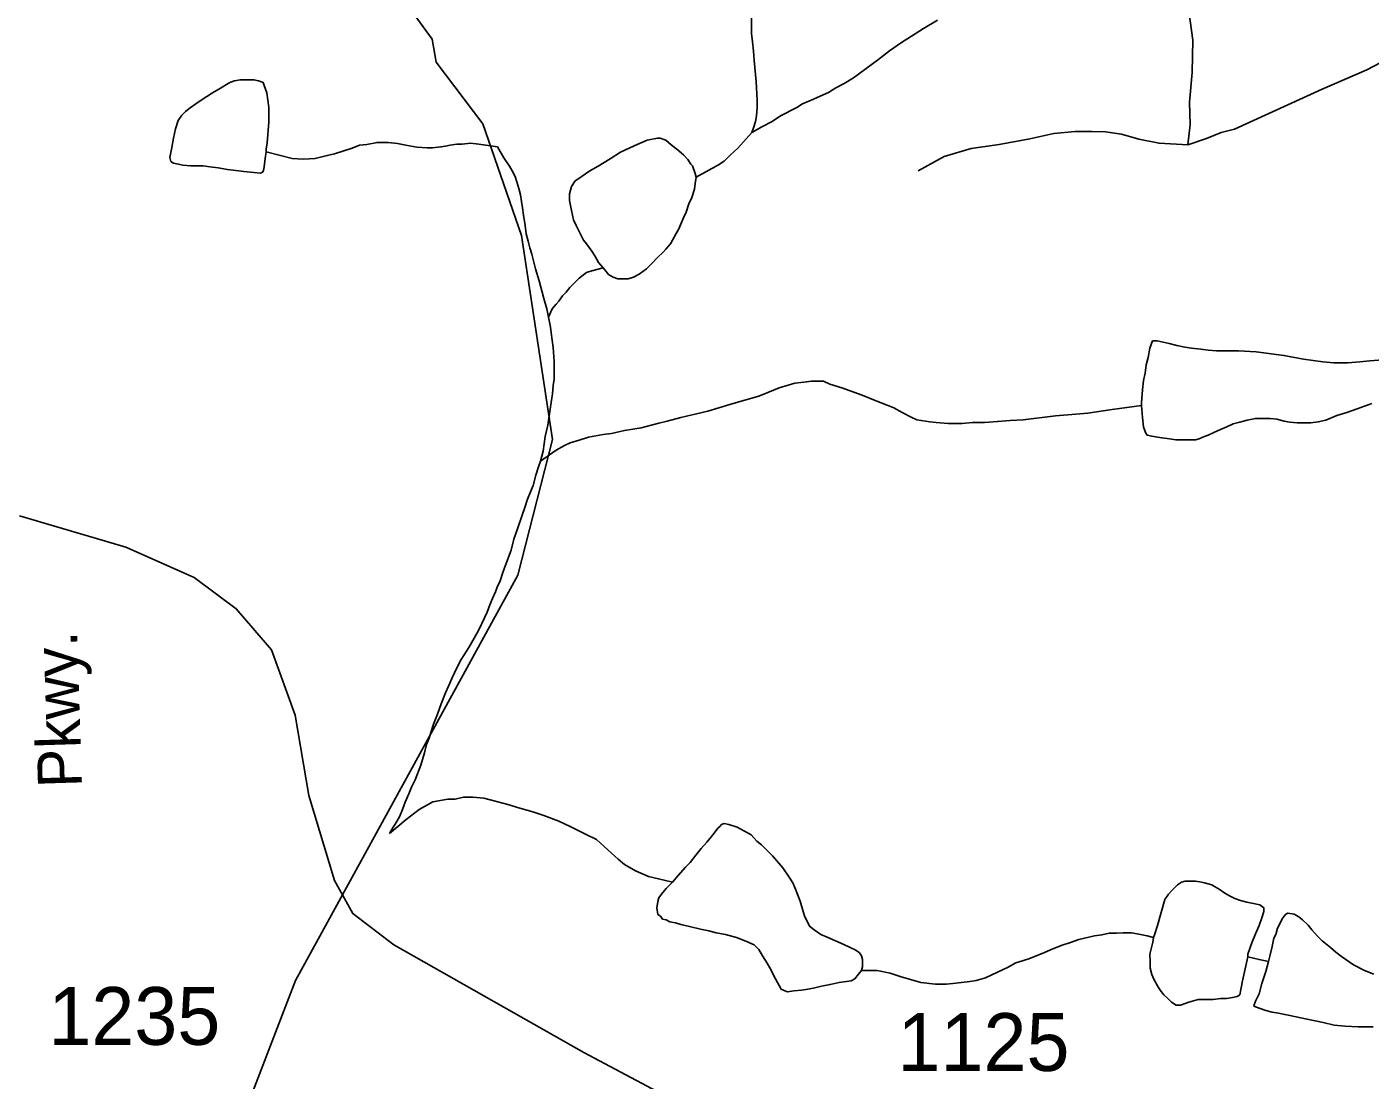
# Model space of a CAD drawing. Extents: x 2001466 to 2224147, y 644118 to 847247.
# Drawn here: x 2043124 to 2046028, y 676608 to 678885 of the extents above; entities that cross this region are included whole.
import ezdxf

# ---------------------------------------------------------------- set-up
doc = ezdxf.new("R2010")
doc.units = 0
for name, color, linetype in [('Exist Hydrographic Creek Single Shore', 7, 'Continuous'), ('Exist Hydrographic Misc Water Feature', 7, 'Continuous'), ('Exist Road Non-System Type 51', 7, 'Continuous'), ('Exist Road Secondary Type 51 Attributed', 7, 'Continuous'), ('Exist Road Secondary Type 51 Label', 7, 'Continuous'), ('Exist Road Secondary Type 51 Number Label', 7, 'Continuous')]:
    doc.layers.add(name, color=color, linetype=linetype)

msp = doc.modelspace()

# ---------------------------------------------------------------- linework, layer by layer
at = {"layer": 'Exist Hydrographic Creek Single Shore'}
for points in [[(2044109.7, 678675.3), (2044008.8, 678808.5), (2044000.8, 678857.9), (2043891.7, 679007.8), (2043766.8, 679272.8)], [(2042616.7, 674673.3), (2042674.7, 674796.8), (2042699.7, 675048.9), (2042799.6, 675214.3), (2043173.6, 675564.3), (2043455.8, 676175.3), (2043704.7, 676823.2), (2044185.7, 677699.3), (2044260.8, 677993), (2044193.7, 678434), (2044109.7, 678675.3)]]:
    msp.add_lwpolyline(points, dxfattribs=at)
at = {"layer": 'Exist Hydrographic Misc Water Feature'}
for points in [[(2044690.8, 678914.4), (2044690.8, 678870.3), (2044693, 678852.3), (2044694.9, 678832.4), (2044696.9, 678812.4), (2044701, 678766.4), (2044703.3, 678726.4), (2044703.3, 678710.4), (2044701.3, 678692.4), (2044699.2, 678680.4), (2044695.3, 678666.4), (2044691.4, 678656.4)], [(2045092.7, 678899.1), (2045063, 678881.1), (2045036.9, 678865), (2045014.8, 678850.9), (2044988.9, 678832.9), (2044962.9, 678812.9), (2044911, 678774.8), (2044891.1, 678762.7), (2044873.1, 678752.7), (2044857.1, 678742.7), (2044839, 678734.7), (2044825.1, 678728.6), (2044801.3, 678718.6), (2044789.2, 678710.6), (2044753.3, 678692.5), (2044735.3, 678680.5), (2044713.1, 678668.4), (2044691.4, 678656.4)], [(2043641.5, 678614.5), (2043639.7, 678600.4), (2043637.6, 678582.4), (2043635.6, 678574.5), (2043633.5, 678570.5), (2043629.6, 678568.5), (2043593.6, 678572.3), (2043575.7, 678574.3), (2043557.7, 678576.3), (2043537.6, 678580.3), (2043519.5, 678582.2), (2043505.6, 678584.2), (2043477.7, 678584.1), (2043461.7, 678586.1), (2043451.7, 678588.1), (2043441.6, 678590.1), (2043435.7, 678594.1), (2043433.6, 678602.1), (2043437.7, 678624.1), (2043441.6, 678644.1), (2043445.5, 678664.1), (2043451.5, 678682.1), (2043459.5, 678694.1), (2043467.5, 678702.1), (2043477.3, 678710.1), (2043489.4, 678718.1), (2043501.3, 678726.1), (2043525.3, 678742.2), (2043539.4, 678750.2), (2043563.4, 678764.3), (2043573.5, 678768.3), (2043585.2, 678770.3), (2043605.2, 678770.3), (2043615.3, 678770.4), (2043625.3, 678768.4), (2043635.2, 678764.4), (2043637.4, 678758.4), (2043643.4, 678742.4), (2043645.4, 678726.4), (2043647.3, 678710.5), (2043647.3, 678694.5), (2043647.5, 678678.5), (2043643.6, 678634.5), (2043641.5, 678620.5), (2043641.5, 678614.5)], [(2043641.5, 678614.5), (2043697.5, 678600.5), (2043721.7, 678598.6), (2043747.6, 678600.6), (2043773.6, 678606.7), (2043789.6, 678610.7), (2043827.5, 678622.8), (2043843.5, 678628.8), (2043859.5, 678630.8), (2043881.5, 678634.9), (2043905.4, 678634.9), (2043925.5, 678633), (2043943.6, 678629), (2043967.6, 678625), (2043989.5, 678623.1), (2044001.4, 678623.1), (2044019.5, 678625.2), (2044029.5, 678627.1), (2044039.5, 678629.1), (2044053.5, 678631.2), (2044065.6, 678631.2), (2044083.4, 678633.3), (2044101.5, 678631.3), (2044141.5, 678625.4)], [(2044571.5, 678560.1), (2044569.4, 678568.1), (2044563.5, 678584.2), (2044559.6, 678588.2), (2044553.4, 678598.2), (2044543.6, 678608.1), (2044529.4, 678620.1), (2044517.3, 678630), (2044505.4, 678640.1), (2044493.3, 678644.1), (2044487.4, 678644), (2044465.4, 678640), (2044437.3, 678627.9), (2044407.4, 678613.9), (2044385.5, 678599.9), (2044359.4, 678583.8), (2044341.6, 678573.7), (2044315.5, 678555.7), (2044309.6, 678551.7), (2044301.6, 678539.6), (2044297.7, 678523.6), (2044297.7, 678509.7), (2044301.8, 678487.7), (2044305.7, 678467.7), (2044311.7, 678455.7), (2044319.6, 678439.7), (2044327.9, 678423.7), (2044333.8, 678415.8), (2044345.9, 678399.8), (2044351.8, 678389.8), (2044359.8, 678375.8), (2044369.9, 678363.9)], [(2044691.4, 678656.4), (2044661.3, 678622.4), (2044645.3, 678608.3), (2044631.5, 678594.3), (2044619.4, 678586.3), (2044571.5, 678560.1)], [(2044141.5, 678625.4), (2044155.4, 678601.4), (2044167.5, 678583.4), (2044173.7, 678573.4), (2044179.6, 678561.5), (2044183.7, 678549.5), (2044187.6, 678535.5), (2044191.7, 678521.5), (2044193.5, 678507.5), (2044195.8, 678493.5), (2044197.6, 678477.5), (2044201.7, 678455.5), (2044203.8, 678437.5), (2044207.9, 678421.5), (2044211.8, 678407.5), (2044215.9, 678393.5), (2044223.9, 678361.6), (2044231.9, 678335.6), (2044241.9, 678297.6), (2044248.1, 678275.6), (2044252.2, 678257.6)], [(2044369.9, 678363.9), (2044373.8, 678359.9), (2044382, 678349.9), (2044392, 678343.9), (2044402.1, 678339.9), (2044410.1, 678339.9), (2044424, 678339.9), (2044435.9, 678344), (2044447.8, 678350), (2044463.8, 678362.1), (2044473.8, 678372.1), (2044487.8, 678386.1), (2044499.9, 678398.1), (2044505.8, 678404.1), (2044515.7, 678416.1), (2044519.8, 678424.1), (2044527.8, 678438.1), (2044533.7, 678448.1), (2044539.7, 678462.2), (2044543.8, 678472.2), (2044549.5, 678484.2), (2044555.7, 678502.2), (2044561.6, 678516.2), (2044567.6, 678534.2), (2044569.4, 678546.2), (2044571.5, 678560.1)], [(2044369.9, 678363.9), (2044345.9, 678357.8), (2044334, 678353.8), (2044318, 678341.7), (2044310, 678333.7), (2044297.9, 678321.7), (2044289.9, 678311.7), (2044281.9, 678303.7), (2044274.1, 678291.7), (2044268.2, 678285.7), (2044260.2, 678275.6), (2044252.2, 678257.6)], [(2044252.2, 678257.6), (2044256.1, 678235.7), (2044258.1, 678223.7), (2044262.2, 678191.7), (2044264.3, 678161.7), (2044264.3, 678139.7), (2044264.3, 678123.6), (2044262.4, 678109.6), (2044260.4, 678091.7), (2044256.5, 678063.7), (2044250.5, 678023.7), (2044244.6, 677999.6), (2044242.5, 677983.6), (2044240.5, 677967.7), (2044234.8, 677945.7)], [(2045534.2, 678066.1), (2045534.2, 678072.1), (2045536.2, 678100.1), (2045538.1, 678120.1), (2045542.2, 678136), (2045544, 678154), (2045548.1, 678170.1), (2045552, 678190.1), (2045558, 678206.1), (2045568, 678206.1), (2045594, 678200.1), (2045610, 678196.2), (2045627.9, 678192.2), (2045642, 678190.2), (2045661.9, 678188.2), (2045677.9, 678186.3), (2045696, 678184.3), (2045743.9, 678184.4), (2045781.9, 678182.5), (2045842, 678174.5), (2045884, 678166.7), (2045926, 678160.8), (2045950, 678158.8), (2045980, 678158.9), (2046006, 678160.9), (2046027.9, 678163), (2046056, 678165)], [(2045534.2, 678066.1), (2045470.2, 678057.9), (2045418.1, 678049.8), (2045392.3, 678047.8), (2045348.4, 678043.7), (2045278.3, 678035.6), (2045250.4, 678033.6), (2045222.3, 678031.5), (2045194.4, 678029.4), (2045168.4, 678029.4), (2045146.4, 678027.4), (2045116.3, 678027.3), (2045090.4, 678029.3), (2045076.3, 678031.2), (2045048.4, 678035.2), (2045036.3, 678041.1), (2045016.4, 678051.1), (2044998.4, 678061.1), (2044984.4, 678067), (2044958.4, 678077), (2044930.3, 678088.9), (2044886.2, 678104.9), (2044860.2, 678112.8), (2044846.2, 678118.7), (2044820.2, 678118.7), (2044804.2, 678116.7), (2044784.3, 678114.7), (2044770.1, 678110.6), (2044750.3, 678104.6), (2044726.3, 678094.5), (2044706.4, 678086.5), (2044678.3, 678078.5), (2044644.2, 678068.4), (2044596.5, 678054.3), (2044562.4, 678046.2), (2044538.4, 678040.2), (2044508.5, 678032.2), (2044490.5, 678028.1), (2044452.5, 678018), (2044416.4, 678012), (2044388.5, 678005.9), (2044370.5, 678003.9), (2044338.5, 677997.8), (2044318.6, 677991.8), (2044298.5, 677985.8), (2044286.6, 677979.7), (2044268.6, 677969.7), (2044234.8, 677945.7)], [(2046032, 678070.9), (2046000.3, 678058.9), (2045978.1, 678050.9), (2045956.2, 678044.8), (2045932.2, 678034.8), (2045916.2, 678030.8), (2045900.2, 678028.8), (2045882.1, 678028.7), (2045870.3, 678028.7), (2045854.3, 678030.7), (2045842.2, 678032.7), (2045826.2, 678036.5), (2045812.2, 678038.5), (2045796.2, 678038.5), (2045780.2, 678038.5), (2045762.2, 678034.5), (2045746.2, 678030.4), (2045732.3, 678026.4), (2045718.3, 678020.4), (2045704.4, 678014.4), (2045690.4, 678008.3), (2045678.3, 678002.3), (2045668.3, 677998.3), (2045658.4, 677994.3), (2045650.4, 677992.3), (2045636.3, 677992.3), (2045620.3, 677992.2), (2045608.4, 677992.2), (2045594.3, 677994.2), (2045578.3, 677996.2), (2045568.4, 677998.2), (2045556.3, 678000.2), (2045546.3, 678002), (2045542.4, 678008), (2045538.3, 678020), (2045536.2, 678040.1), (2045534.2, 678066.1)], [(2044234.8, 677945.7), (2044230.7, 677933.7), (2044224.7, 677915.7), (2044218.8, 677893.7), (2044212.8, 677879.7), (2044206.9, 677863.6), (2044200.9, 677845.6), (2044194.8, 677829.6), (2044184.9, 677799.6), (2044176.9, 677777.6), (2044171.2, 677753.6), (2044159.1, 677721.5), (2044153.1, 677705.5), (2044147.2, 677687.5), (2044141.3, 677673.6), (2044137.2, 677663.6), (2044131.2, 677649.5), (2044125.3, 677635.5), (2044119.3, 677619.5), (2044113.4, 677607.5), (2044101.3, 677581.5), (2044091.4, 677563.5), (2044079.5, 677543.4), (2044069.5, 677527.4), (2044063.5, 677517.4), (2044053.5, 677499.4), (2044043.6, 677477.4), (2044035.7, 677459.4), (2044029.5, 677445.3), (2044019.7, 677421.3), (2044011.7, 677399.3), (2044003.7, 677377.4), (2043997.9, 677359.4), (2043993.8, 677347.4), (2043987.9, 677333.3), (2043983.8, 677315.3), (2043976, 677289.3), (2043963.9, 677257.3), (2043955.9, 677241.3), (2043950.1, 677227.3), (2043942.1, 677209.2), (2043936, 677193.2), (2043930, 677177.2), (2043920.2, 677161.2), (2043916.1, 677155.2), (2043908.1, 677141.2)], [(2043908.1, 677141.2), (2043944, 677171.3), (2043972.1, 677193.3), (2044002, 677209.4), (2044034, 677215.4), (2044050, 677215.5), (2044068, 677219.5), (2044088.1, 677219.5), (2044111.9, 677217.5), (2044142.1, 677209.6), (2044164, 677203.7), (2044190.1, 677195.7), (2044218.1, 677187.8), (2044242.1, 677179.8), (2044274.1, 677167.8), (2044300.2, 677155.9), (2044332.2, 677140), (2044356.1, 677128.1), (2044380.1, 677106.1), (2044402.3, 677086.1), (2044416.2, 677074.2), (2044440.2, 677060.2), (2044468.1, 677048.2), (2044502.3, 677040.3), (2044520.4, 677036.4)], [(2044520.4, 677036.4), (2044532.3, 677050.4), (2044548.3, 677068.4), (2044558.1, 677078.4), (2044570.2, 677094.4), (2044582.1, 677108.5), (2044594, 677122.5), (2044604.1, 677134.5), (2044612.1, 677144.5), (2044618, 677152.5), (2044622.1, 677156.6), (2044626, 677160.6), (2044632.1, 677162.6), (2044642, 677160.6), (2044660, 677154.6), (2044676, 677146.6), (2044690, 677138.7), (2044702.1, 677124.7), (2044712.1, 677116.7), (2044736.1, 677092.7), (2044758.3, 677066.8), (2044772.2, 677046.8), (2044780.2, 677034.9), (2044786.1, 677020.9), (2044796.4, 676994.9), (2044802.3, 676972.8), (2044806.2, 676960.9), (2044812.4, 676949), (2044816.5, 676940.9), (2044826.5, 676932.9), (2044840.5, 676923), (2044854.4, 676917), (2044872.5, 676909.1), (2044890.5, 676901.1), (2044904.5, 676895.1), (2044916.3, 676889.1), (2044924.3, 676883.1), (2044928.4, 676877.1), (2044930.5, 676869.1), (2044930.5, 676853.1), (2044928.7, 676845.1)], [(2044928.7, 676845.1), (2044922.5, 676837.1), (2044914.5, 676827.1), (2044906.5, 676823.1), (2044880.5, 676819.1), (2044860.6, 676815), (2044842.5, 676811), (2044824.7, 676806.9), (2044812.6, 676804.9), (2044798.6, 676802.9), (2044782.7, 676800.9), (2044768.7, 676798.9), (2044762.8, 676800.9), (2044754.8, 676804.8), (2044742.5, 676826.8), (2044730.6, 676850.8), (2044724.6, 676860.7), (2044714.6, 676876.7), (2044706.4, 676890.7), (2044696.5, 676900.7), (2044678.5, 676908.7), (2044658.4, 676916.6), (2044634.4, 676922.6), (2044614.5, 676926.5), (2044598.5, 676930.5), (2044580.5, 676934.5), (2044556.5, 676940.4), (2044538.4, 676944.4), (2044526.3, 676948.3), (2044514.4, 676950.3), (2044506.5, 676954.3), (2044498.5, 676956.3), (2044494.4, 676962.3), (2044488.4, 676966.3), (2044486.4, 676980.3), (2044488.4, 676994.3), (2044490.3, 677002.3), (2044496.4, 677010.3), (2044506.2, 677022.4), (2044520.4, 677036.4)], [(2045764.2, 676874.7), (2045764.2, 676880.7), (2045772.2, 676904.7), (2045780.2, 676924.7), (2045788.2, 676942.7), (2045794.2, 676958.7), (2045798.3, 676972.7), (2045798.3, 676980.8), (2045790.1, 676986.7), (2045772.2, 676990.7), (2045762, 676992.6), (2045748, 676996.6), (2045736.1, 677000.6), (2045724, 677006.6), (2045714, 677012.6), (2045702.1, 677020.6), (2045692.1, 677026.5), (2045686.1, 677030.5), (2045670.1, 677034.5), (2045660.1, 677036.5), (2045650, 677038.5), (2045640, 677038.5), (2045628.1, 677038.4), (2045620.1, 677036.4), (2045612.1, 677030.4), (2045600, 677018.4), (2045592, 677010.3), (2045584.2, 676998.3), (2045568.2, 676942.3), (2045562.3, 676922.3), (2045560.2, 676916.3)], [(2045808.3, 676864.8), (2045812.2, 676878.8), (2045816.3, 676896.8), (2045820.2, 676914.8), (2045824.1, 676922.8), (2045828.2, 676936.8), (2045834.2, 676948.8), (2045838.3, 676956.8), (2045842.2, 676962.8), (2045846.3, 676966.8), (2045850.2, 676968.8), (2045864.1, 676966.9), (2045874.1, 676960.9), (2045882.1, 676954.9), (2045894.2, 676942.9), (2045902.2, 676933), (2045914.1, 676919), (2045924.2, 676909), (2045942.2, 676895), (2045954.3, 676885), (2045966.2, 676875.1), (2045992.3, 676857.1), (2046016.2, 676845.1), (2046036.3, 676837.2)], [(2044928.7, 676845.1), (2044962.5, 676845.2), (2044990.6, 676839.2), (2045014.6, 676831.3), (2045034.5, 676825.4), (2045056.6, 676819.4), (2045088.6, 676815.4), (2045112.6, 676815.5), (2045132.5, 676817.5), (2045162.6, 676821.6), (2045176.6, 676823.6), (2045196.7, 676829.6), (2045222.5, 676841.7), (2045244.4, 676851.8), (2045262.5, 676861.8), (2045288.5, 676869.8), (2045308.4, 676877.8), (2045324.4, 676883.9), (2045342.4, 676891.9), (2045362.3, 676899.9), (2045380.4, 676905.9), (2045398.2, 676912), (2045432.3, 676920.1), (2045448.3, 676922.1), (2045464.2, 676926.1), (2045480.2, 676926.1), (2045494.4, 676926.2), (2045512.2, 676926.2), (2045524.3, 676924.2), (2045546.3, 676920.2), (2045560.2, 676916.3)], [(2045560.2, 676916.3), (2045558.4, 676906.3), (2045552.2, 676880.3), (2045552.4, 676864.3), (2045552.4, 676850.3), (2045556.5, 676836.3), (2045560.4, 676826.3), (2045568.4, 676812.3), (2045574.6, 676802.3), (2045582.6, 676792.4), (2045590.6, 676784.4), (2045598.6, 676776.4), (2045608.6, 676770.5), (2045618.4, 676770.5), (2045636.5, 676776.5), (2045656.6, 676782.5), (2045674.6, 676782.5), (2045688.6, 676782.6), (2045704.6, 676784.6), (2045718.5, 676784.7), (2045730.6, 676786.7), (2045740.5, 676788.7), (2045746.4, 676792.7), (2045752.3, 676822.7), (2045764.2, 676874.7)], [(2045764.2, 676874.7), (2045788.2, 676868.8), (2045808.3, 676864.8)], [(2046034.5, 676723.2), (2046002.5, 676723.1), (2045974.6, 676725.1), (2045950.6, 676727.1), (2045926.6, 676733), (2045888.5, 676740.9), (2045868.6, 676744.9), (2045830.5, 676752.8), (2045816.5, 676754.8), (2045802.6, 676758.8), (2045790.5, 676762.8), (2045780.6, 676766.8), (2045776.5, 676768.7), (2045780.6, 676778.8), (2045788.4, 676794.8), (2045794.4, 676816.7), (2045802.4, 676842.8), (2045808.3, 676864.8)]]:
    msp.add_lwpolyline(points, dxfattribs=at)
at = {"layer": 'Exist Road Non-System Type 51'}
for points in [[(2045616.8, 680536.4), (2045605.2, 680262.7), (2045587.3, 679973), (2045573.7, 679695.3), (2045578, 679515.2), (2045578.6, 679349.2), (2045578.3, 679233.2), (2045583, 679169.1), (2045584.2, 679131.1), (2045593.4, 679090.9), (2045604.3, 679036.7), (2045623.1, 678980.3), (2045632.4, 678946.1), (2045639.4, 678898), (2045644.6, 678855.9), (2045643.2, 678785.9), (2045637.9, 678722), (2045638.9, 678674), (2045634, 678630.1)], [(2046079.9, 678823), (2046021.3, 678792.2), (2045924.4, 678750.2), (2045734.7, 678664), (2045706.5, 678656.6), (2045674.3, 678643.3), (2045634, 678630.1)], [(2045634, 678630.1), (2045572.1, 678633.3), (2045528.2, 678642.2), (2045490.5, 678653), (2045456.5, 678657.7), (2045426.6, 678658.3), (2045390.6, 678659), (2045344.5, 678654), (2045292.2, 678643), (2045226, 678630.4), (2045165.8, 678621.6), (2045107.5, 678604.8), (2045050.8, 678573.9)]]:
    msp.add_lwpolyline(points, dxfattribs=at)
at = {"layer": 'Exist Road Secondary Type 51 Attributed'}
msp.add_lwpolyline([(2046282.6, 675627.7), (2046203.9, 675670.6), (2044328.5, 676668), (2043917.8, 676900.4), (2043829.2, 676968), (2043789.1, 677039.9), (2043734.2, 677223.7), (2043704.6, 677396.9), (2043652.9, 677538.4), (2043576.9, 677627.2), (2043486.1, 677694.8), (2043338.3, 677760.3), (2043108.3, 677828)], dxfattribs=at)

# ---------------------------------------------------------------- texts
at = {"layer": 'Exist Road Secondary Type 51 Label'}
msp.add_text('Pkwy.', height=95, rotation=91.7822, dxfattribs=at).set_placement((2043243.5, 677241.4))
at = {"layer": 'Exist Road Secondary Type 51 Number Label'}
for s, p in [('1235', (2043170.6, 676684.4)), ('1125', (2045006.4, 676627.9))]:
    msp.add_text(s, height=125, dxfattribs=at).set_placement(p)

doc.saveas('drawing.dxf')
